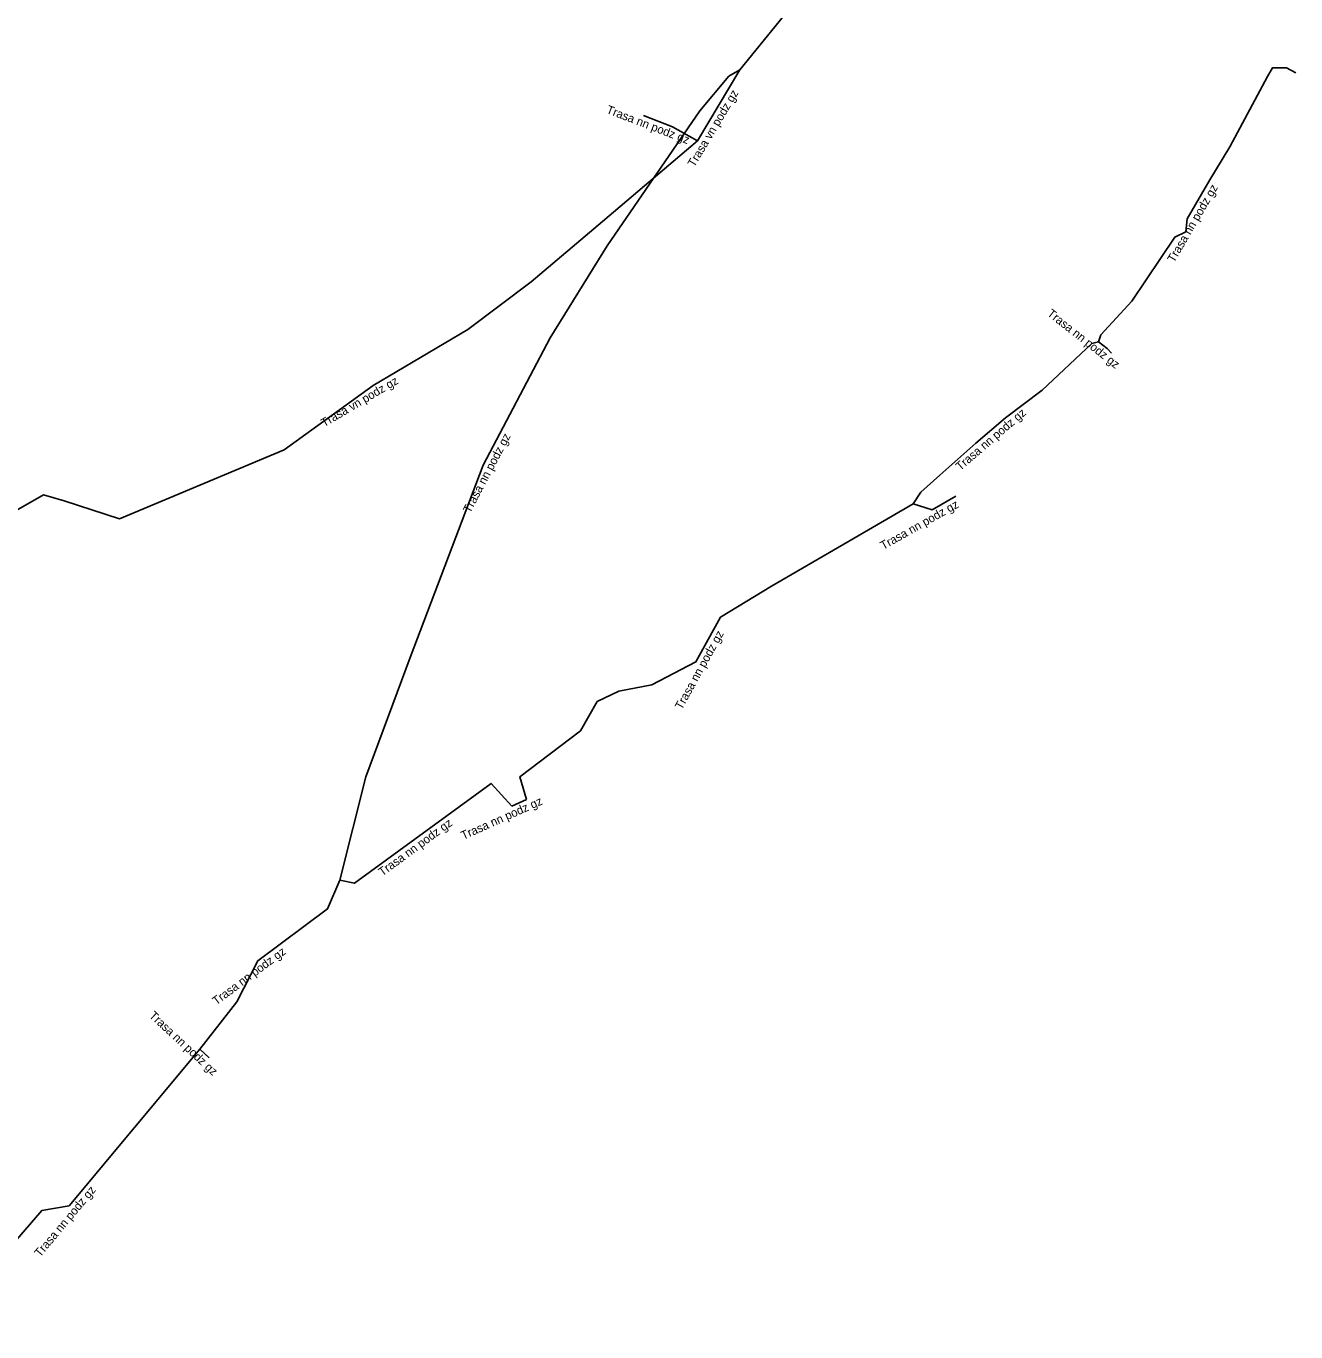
# Model space of a CAD drawing. Extents: x -688315 to -687940, y -1059595 to -1059240.
# Drawn here: x -688055.8 to -687981, y -1059436.1 to -1059359.3 of the extents above; entities that cross this region are included whole.
import ezdxf

# ---------------------------------------------------------------- set-up
doc = ezdxf.new("R2010")
doc.units = 0
for name, color, linetype in [('Popiskový text - Ostatní atributy Trasy', 7, 'Continuous'), ('Spojnice NN', 7, 'Continuous'), ('Spojnice VN', 7, 'Continuous')]:
    doc.layers.add(name, color=color, linetype=linetype)

msp = doc.modelspace()

# ---------------------------------------------------------------- linework, layer by layer
at = {"layer": 'Spojnice NN'}
for points in [[(-688013.78, -1059361.85), (-688014.42, -1059362.22), (-688016.12, -1059364.27), (-688021.58, -1059372.2), (-688024.94, -1059377.62), (-688028.88, -1059385.11), (-688033.17, -1059396.44), (-688035.79, -1059403.46), (-688037.31, -1059409.53)], [(-687981.04, -1059362.03), (-687981.6, -1059361.73), (-687982.41, -1059361.73), (-687982.72, -1059362.24), (-687984.93, -1059366.38), (-687986.1, -1059368.32), (-687987.44, -1059370.62), (-687987.52, -1059371.39), (-687988.17, -1059371.69), (-687990.69, -1059375.47), (-687992.53, -1059377.44), (-687992.66, -1059377.85)], [(-688016.26, -1059366.02), (-688017.73, -1059365.2), (-688019.45, -1059364.54)], [(-687992.66, -1059377.85), (-687993.05, -1059377.96), (-687995.98, -1059380.7), (-687998.14, -1059382.33), (-687999.89, -1059383.83), (-688002, -1059385.71), (-688003.12, -1059386.7), (-688003.56, -1059387.4)], [(-687991.901, -1059378.532), (-687992.15, -1059378.25), (-687992.66, -1059377.85)], [(-688003.56, -1059387.4), (-688007.05, -1059389.42), (-688011.91, -1059392.24), (-688014.91, -1059394.06), (-688016.36, -1059396.69), (-688018.95, -1059398.04), (-688020.9, -1059398.41), (-688022.17, -1059399.03), (-688023.15, -1059400.74), (-688026.73, -1059403.46), (-688026.33, -1059404.79)], [(-688003.56, -1059387.4), (-688002.46, -1059387.74), (-688001.06, -1059386.947)], [(-688037.31, -1059409.53), (-688036.46, -1059409.72), (-688028.42, -1059403.84), (-688027.2, -1059405.18)], [(-688027.2, -1059405.18), (-688026.33, -1059404.79)], [(-688037.31, -1059409.53), (-688038.04, -1059411.23), (-688042.14, -1059414.28), (-688043.39, -1059416.69), (-688045.56, -1059419.48)], [(-688045.56, -1059419.48), (-688053.26, -1059428.7), (-688054.87, -1059428.98), (-688059.16, -1059433.94), (-688061.07, -1059436.12)], [(-688045.01, -1059419.99), (-688045.56, -1059419.48)]]:
    msp.add_lwpolyline(points, dxfattribs=at)
at = {"layer": 'Spojnice VN'}
for points in [[(-688013.78, -1059361.85), (-688010.27, -1059357.52), (-688006.59, -1059352.82), (-688002.97, -1059346.44), (-687999.83, -1059339.55), (-687998.26, -1059336.22)], [(-688016.26, -1059366.02), (-688013.78, -1059361.85)], [(-688056.51, -1059387.87), (-688054.76, -1059386.87), (-688053.54, -1059387.22), (-688050.29, -1059388.27), (-688040.59, -1059384.22), (-688035.35, -1059380.43), (-688029.78, -1059377.14), (-688026.06, -1059374.33), (-688021.86, -1059370.77), (-688016.26, -1059366.02)]]:
    msp.add_lwpolyline(points, dxfattribs=at)

# ---------------------------------------------------------------- texts
at = {"layer": 'Popiskový text - Ostatní atributy Trasy'}
for s, rotation, p in [('Trasa vn podz gz', 59.25903, (-688016.451, -1059367.613)), ('Trasa nn podz gz', 339.00715, (-688021.673, -1059364.383)), ('Trasa nn podz gz', 59.77455, (-687988.208, -1059373.23)), ('Trasa nn podz gz', 321.89242, (-687995.722, -1059376.275)), ('Trasa vn podz gz', 30.56883, (-688038.242, -1059382.893)), ('Trasa nn podz gz', 40.60129, (-688000.799, -1059385.465)), ('Trasa nn podz gz', 62.25407, (-688029.65, -1059387.971)), ('Trasa nn podz gz', 29.52846, (-688005.329, -1059390.112)), ('Trasa nn podz gz', 61.1307, (-688017.191, -1059399.543)), ('Trasa nn podz gz', 24.14554, (-688030.052, -1059407.171)), ('Trasa nn podz gz', 36.17962, (-688034.819, -1059409.325)), ('Trasa nn podz gz', 36.64565, (-688044.591, -1059416.914)), ('Trasa nn podz gz', 317.16108, (-688048.582, -1059417.564)), ('Trasa nn podz gz', 50.13336, (-688054.961, -1059431.752))]:
    msp.add_text(s, height=0.5, rotation=rotation, dxfattribs=at).set_placement(p)

doc.saveas('drawing.dxf')
